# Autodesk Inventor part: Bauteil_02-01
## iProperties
Created: 2007-04
Part Number: Bauteil_02-01
Document SubType Name: Modeling
Designer: Sascha Fleischer
Author: Sascha Fleischer
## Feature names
1. Extrusion1
